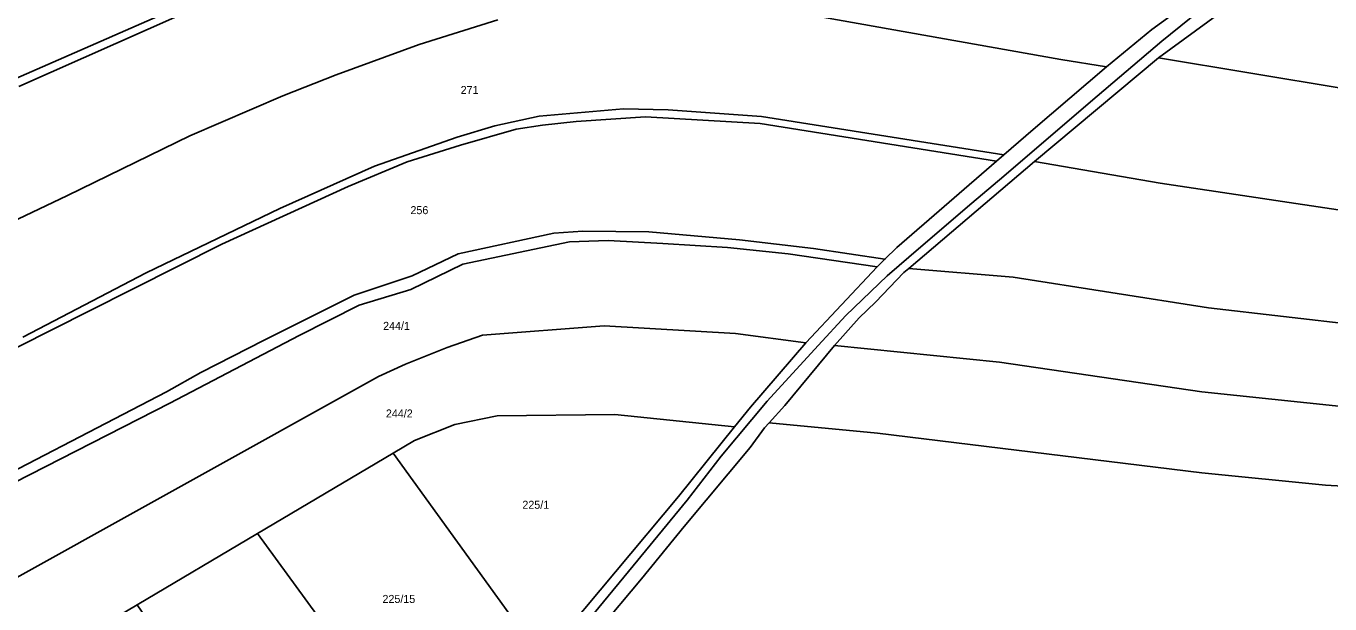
# Model space of a CAD drawing. Extents: x -629983 to -626385, y -1072828 to -1067897.
# Drawn here: x -628779.1 to -628290.3, y -1071180 to -1070963.6 of the extents above; entities that cross this region are included whole.
import ezdxf

# ---------------------------------------------------------------- set-up
doc = ezdxf.new("R2010")
doc.units = 0
for name, color, linetype in [('Parcela nároku', 7, 'Continuous'), ('Parcelní číslo', 7, 'Continuous'), ('silnice III třídy', 7, 'Continuous')]:
    doc.layers.add(name, color=color, linetype=linetype)

msp = doc.modelspace()

# ---------------------------------------------------------------- linework, layer by layer
at = {"layer": 'Parcela nároku'}
for points in [[(-628781.86, -1070986.24), (-628696.9, -1070948.55), (-628671.44, -1070938.84), (-628628.48, -1070923.55), (-628602.77, -1070915.65), (-628585.16, -1070911.63), (-628553.52, -1070907.62), (-628531.29, -1070906.78), (-628510.62, -1070909.12), (-628455.75, -1070917.07), (-628324.42, -1070941.18), (-628320.82, -1070938.58), (-628391.5, -1070925.19), (-628490.51, -1070908.74), (-628515.29, -1070905.61), (-628538.83, -1070903.72), (-628562.42, -1070905.84), (-628592.03, -1070910.52), (-628609.91, -1070914.99), (-628625.85, -1070920.13), (-628672.98, -1070936.41), (-628713.88, -1070952.86), (-628846.18, -1071010.81)], [(-628779.81, -1071363.77), (-628758.9, -1071347.23), (-628745.51, -1071336.42), (-628729.51, -1071322.9), (-628710.66, -1071307.14), (-628672.51, -1071275.03), (-628629.92, -1071239), (-628597.21, -1071211.52), (-628591.18, -1071206.34), (-628585.76, -1071200.55), (-628581.7, -1071196.21), (-628534.57, -1071139.82), (-628513.46, -1071113.69), (-628507.55, -1071106.37), (-628486.77, -1071082.21), (-628460.07, -1071053.8), (-628457.12, -1071050.9), (-628452.67, -1071046.53), (-628415.32, -1071014.18), (-628412.52, -1071011.79), (-628401.5, -1071002.26), (-628374.03, -1070978.84), (-628357.03, -1070964.86), (-628324.42, -1070941.18)], [(-628486.18, -1070959.2), (-628391.15, -1070976.04), (-628374.03, -1070978.84), (-628357.03, -1070964.86), (-628324.42, -1070941.18)], [(-628696.9, -1070948.55), (-628781.86, -1070986.24)], [(-628713.88, -1070952.86), (-628846.18, -1071010.81)], [(-628486.18, -1070959.2), (-628391.15, -1070976.04), (-628374.03, -1070978.84), (-628401.5, -1071002.26), (-628412.52, -1071011.79), (-628503.34, -1070997.5), (-628538.37, -1070994.97), (-628555.09, -1070994.58), (-628586.72, -1070997.35), (-628603.36, -1071000.92), (-628617.47, -1071005.13), (-628648.45, -1071016.07), (-628683.97, -1071031.92), (-628734.05, -1071056.05), (-628780.34, -1071080.11)], [(-628331.46, -1070958.61), (-628354.57, -1070975.46), (-628401, -1071014.26), (-628448.17, -1071054.33), (-628450.07, -1071055.94), (-628460.69, -1071066.99), (-628466.82, -1071072.83), (-628476.05, -1071083.19), (-628494.61, -1071105.68), (-628500.56, -1071112.2), (-628502.21, -1071114.01), (-628507.6, -1071121.45), (-628532.34, -1071151.07), (-628548.36, -1071170.68), (-628564.48, -1071189.84)], [(-628829.59, -1071058.41), (-628763.6, -1071027.07), (-628717.73, -1071004.63), (-628682.85, -1070989.68), (-628662.87, -1070981.83), (-628631.75, -1070970.42), (-628602.25, -1070961.21)], [(-628829.59, -1071058.41), (-628763.6, -1071027.07), (-628717.73, -1071004.63), (-628682.85, -1070989.68), (-628662.87, -1070981.83), (-628631.75, -1070970.42), (-628602.25, -1070961.21)], [(-628822.02, -1071103.82), (-628755.57, -1071070.38), (-628705.65, -1071045.24), (-628658.31, -1071023.61), (-628636.27, -1071014.44), (-628616.24, -1071008.18), (-628595.31, -1071002.17), (-628585.46, -1071000.65), (-628572.9, -1070999.32), (-628546.82, -1070997.61), (-628503.91, -1071000.06), (-628415.32, -1071014.18), (-628412.52, -1071011.79), (-628503.34, -1070997.5), (-628538.37, -1070994.97), (-628555.09, -1070994.58), (-628586.72, -1070997.35), (-628603.36, -1071000.92), (-628617.47, -1071005.13), (-628648.45, -1071016.07), (-628683.97, -1071031.92), (-628734.05, -1071056.05), (-628780.34, -1071080.11)], [(-628807.94, -1071142.79), (-628726.4, -1071100.56), (-628713.54, -1071093.31), (-628689.83, -1071081.24), (-628656.11, -1071064.31), (-628634.36, -1071057.18), (-628617.07, -1071048.92), (-628581.21, -1071041.17), (-628570.37, -1071040.4), (-628545.6, -1071040.66), (-628511.62, -1071043.59), (-628483.84, -1071046.95), (-628457.12, -1071050.9), (-628452.67, -1071046.53), (-628415.32, -1071014.18), (-628503.91, -1071000.06), (-628546.82, -1070997.61), (-628572.9, -1070999.32), (-628585.46, -1071000.65), (-628595.31, -1071002.17), (-628616.24, -1071008.18), (-628636.27, -1071014.44), (-628658.31, -1071023.61), (-628705.65, -1071045.24), (-628755.57, -1071070.38), (-628822.02, -1071103.82)], [(-628282.25, -1071033.13), (-628353.97, -1071022.4), (-628401, -1071014.26), (-628448.17, -1071054.33), (-628409, -1071057.64), (-628335.82, -1071069.16), (-628279.62, -1071075.58)], [(-628807.03, -1071146.51), (-628725.21, -1071104.83), (-628676.65, -1071079.49), (-628654.18, -1071068.12), (-628634.85, -1071062.19), (-628615.3, -1071052.73), (-628575.38, -1071044.41), (-628560.82, -1071043.89), (-628540.34, -1071045.04), (-628516.09, -1071046.5), (-628493.4, -1071048.9), (-628460.07, -1071053.8), (-628457.12, -1071050.9), (-628483.84, -1071046.95), (-628511.62, -1071043.59), (-628545.6, -1071040.66), (-628570.37, -1071040.4), (-628581.21, -1071041.17), (-628617.07, -1071048.92), (-628634.36, -1071057.18), (-628656.11, -1071064.31), (-628689.83, -1071081.24), (-628713.54, -1071093.31), (-628726.4, -1071100.56), (-628807.94, -1071142.79)], [(-628272.67, -1071107.46), (-628338.37, -1071100.63), (-628414.23, -1071089.43), (-628476.05, -1071083.19), (-628466.82, -1071072.83), (-628460.69, -1071066.99), (-628450.07, -1071055.94), (-628448.17, -1071054.33), (-628409, -1071057.64), (-628335.82, -1071069.16), (-628279.62, -1071075.58)], [(-628272.67, -1071107.46), (-628338.37, -1071100.63), (-628414.23, -1071089.43), (-628476.05, -1071083.19), (-628494.61, -1071105.68), (-628500.56, -1071112.2), (-628459.92, -1071116.05), (-628338.35, -1071130.97), (-628291.93, -1071135.53), (-628268.25, -1071136.94)], [(-628268.25, -1071136.94), (-628291.93, -1071135.53), (-628338.35, -1071130.97), (-628459.92, -1071116.05), (-628500.56, -1071112.2), (-628502.21, -1071114.01), (-628507.6, -1071121.45), (-628532.34, -1071151.07), (-628548.36, -1071170.68), (-628564.48, -1071189.84), (-628502.34, -1071196.75), (-628482.19, -1071198.25), (-628480.08, -1071198.41), (-628478.48, -1071198.53), (-628427.9, -1071200.4), (-628334.96, -1071209.11), (-628312.3, -1071210.8), (-628248.73, -1071213.64)]]:
    msp.add_lwpolyline(points, dxfattribs=at)
for points in [[(-628331.46, -1070958.61), (-628354.57, -1070975.46), (-628250.75, -1070992.75), (-628210.59, -1070996.63), (-628170.63, -1070998.53), (-628137.42, -1070996.44), (-628108.15, -1070991.5), (-628036.8, -1070976.12), (-628000.12, -1070970.48), (-627993.94, -1070968.01), (-627988.33, -1070964.81), (-627986.83, -1070952.94), (-627984.18, -1070921.67), (-627995.58, -1070929.26), (-628030.61, -1070935.24), (-628078.59, -1070944.87), (-628135.03, -1070952.93), (-628198.8, -1070953.87), (-628250.8, -1070951.29), (-628298.12, -1070946.76), (-628311.98, -1070944.35)], [(-628354.57, -1070975.46), (-628401, -1071014.26), (-628353.97, -1071022.4), (-628282.25, -1071033.13), (-628216.14, -1071040.1), (-628188.19, -1071040.45), (-628170.08, -1071040.01), (-628151.79, -1071039.07), (-628105.09, -1071029.7), (-628050.75, -1071014.99), (-628026.19, -1071009.24), (-627999.19, -1071005.09), (-628000.12, -1070970.48), (-628036.8, -1070976.12), (-628108.15, -1070991.5), (-628137.42, -1070996.44), (-628170.63, -1070998.53), (-628210.59, -1070996.63), (-628250.75, -1070992.75)], [(-628493.4, -1071048.9), (-628460.07, -1071053.8), (-628486.77, -1071082.21), (-628513.11, -1071078.74), (-628562.4, -1071075.91), (-628607.97, -1071079.3), (-628621.27, -1071083.93), (-628636.81, -1071090.23), (-628646.92, -1071094.78), (-628796.16, -1071177.6), (-628807.03, -1071146.51), (-628725.21, -1071104.83), (-628676.65, -1071079.49), (-628654.18, -1071068.12), (-628634.85, -1071062.19), (-628615.3, -1071052.73), (-628575.38, -1071044.41), (-628560.82, -1071043.89), (-628540.34, -1071045.04), (-628516.09, -1071046.5)], [(-628607.97, -1071079.3), (-628562.4, -1071075.91), (-628513.11, -1071078.74), (-628486.77, -1071082.21), (-628507.55, -1071106.37), (-628513.46, -1071113.69), (-628558.39, -1071109.04), (-628602.49, -1071109.6), (-628618.37, -1071112.87), (-628633.45, -1071118.81), (-628641.45, -1071123.56), (-628692.33, -1071153.64), (-628737.5, -1071180.33), (-628778.36, -1071204.62), (-628783.08, -1071207.3), (-628796.16, -1071177.6), (-628646.92, -1071094.78), (-628636.81, -1071090.23), (-628621.27, -1071083.93)], [(-628641.45, -1071123.56), (-628633.45, -1071118.81), (-628618.37, -1071112.87), (-628602.49, -1071109.6), (-628558.39, -1071109.04), (-628513.46, -1071113.69), (-628534.57, -1071139.82), (-628581.7, -1071196.21), (-628585.76, -1071200.55)], [(-628641.45, -1071123.56), (-628585.76, -1071200.55), (-628591.18, -1071206.34), (-628597.21, -1071211.52), (-628629.92, -1071239), (-628692.33, -1071153.64)], [(-628692.33, -1071153.64), (-628737.5, -1071180.33), (-628672.51, -1071275.03), (-628629.92, -1071239)]]:
    msp.add_lwpolyline(points, close=True, dxfattribs=at)
at = {"layer": 'silnice III třídy'}
msp.add_lwpolyline([(-628322.2, -1070943.99), (-628353.36, -1070969.18), (-628380.04, -1070991.96), (-628412.57, -1071019.74), (-628424.5, -1071029.93), (-628443.68, -1071046.32), (-628456.33, -1071057.13), (-628471.81, -1071072.03), (-628482.12, -1071083.25), (-628501.3, -1071104.12), (-628518.52, -1071124.66), (-628531.24, -1071141.2), (-628551.52, -1071165.81), (-628564.37, -1071181.4), (-628576.53, -1071196.16), (-628585.44, -1071205.31), (-628595, -1071213.46), (-628607.34, -1071223.98), (-628624.36, -1071239.11), (-628628.04, -1071242.38), (-628655.8, -1071265.81), (-628739.02, -1071334.83), (-628778.5, -1071366.09), (-628804.76, -1071387.73)], dxfattribs=at)

# ---------------------------------------------------------------- texts
at = {"layer": 'Parcelní číslo'}
for s, p in [('271', (-628616.17, -1070989.01)), ('256', (-628634.99, -1071034.02)), ('244/1', (-628645.23, -1071077.38)), ('244/2', (-628644.19, -1071110.19)), ('225/1', (-628593.03, -1071144.38)), ('225/15', (-628645.47, -1071179.66))]:
    msp.add_text(s, height=3, dxfattribs=at).set_placement(p)

doc.saveas('drawing.dxf')
